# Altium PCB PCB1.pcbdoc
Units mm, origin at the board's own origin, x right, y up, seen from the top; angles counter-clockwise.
Board outline 140.58 x 68.45 mm, 2 copper layers (Top Layer, Bottom Layer); 49 components, 39 nets, 167 pads, 0 vias.
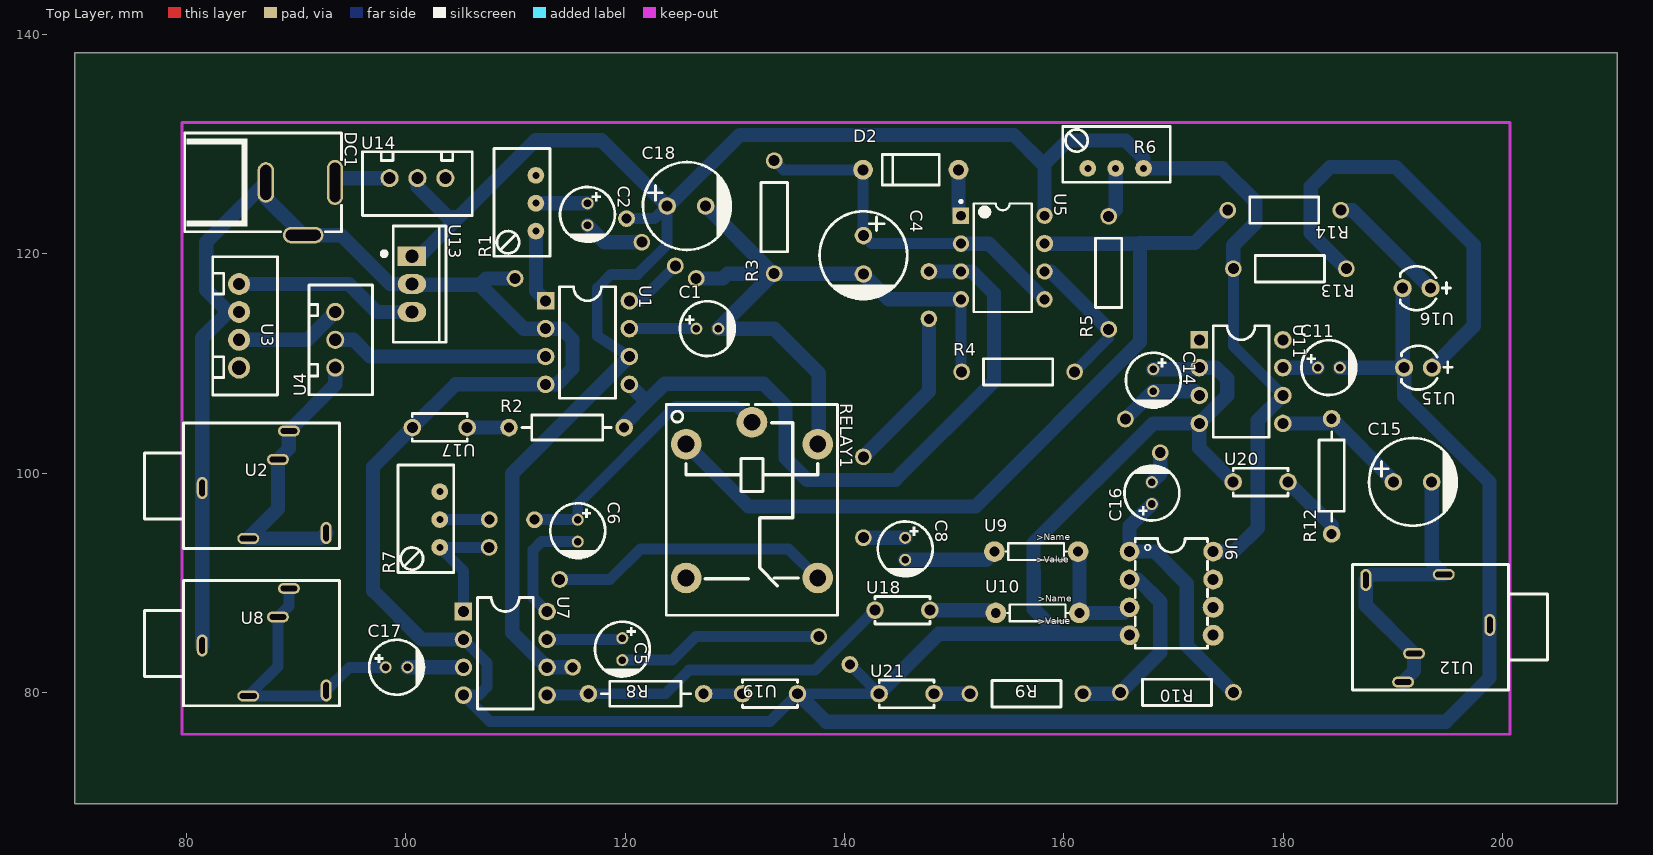
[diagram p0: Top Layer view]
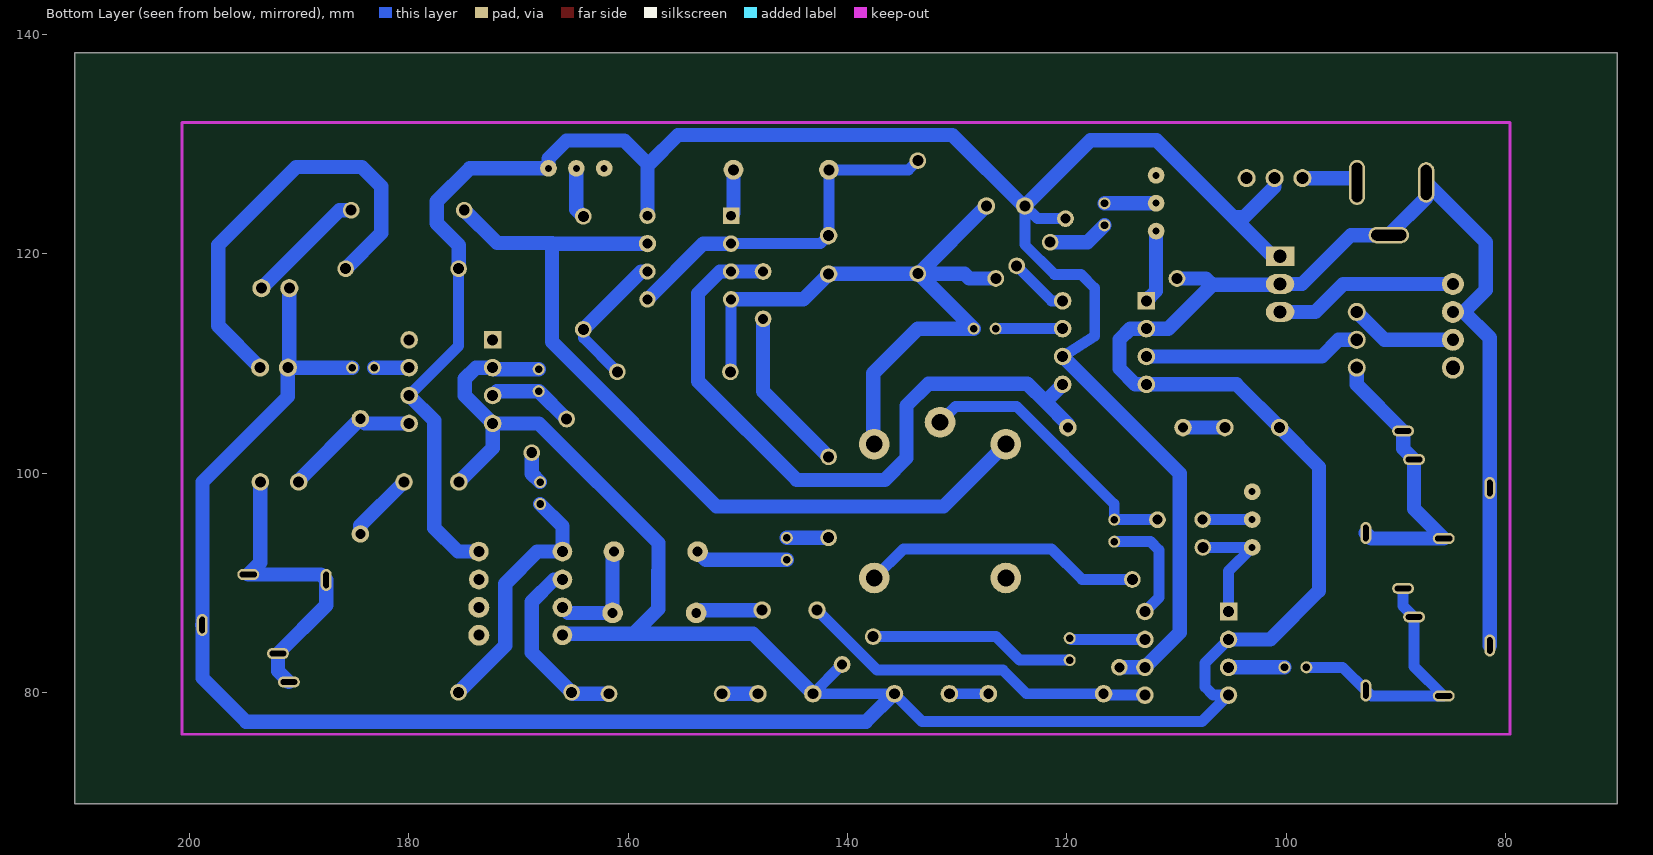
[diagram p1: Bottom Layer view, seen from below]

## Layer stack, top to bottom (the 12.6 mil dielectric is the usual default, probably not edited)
Top Layer: signal copper (thickness not stored)
Dielectric: dielectric 0.32, FR-4, Dk 4.8
Bottom Layer: signal copper (thickness not stored)

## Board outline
210.431,69.85 69.85,69.85 69.85,138.303 210.431,138.303

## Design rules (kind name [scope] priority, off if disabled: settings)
BoardOutlineClearance copperThickness1oz [All] p0: genericclearance=0.254 ignorepadtopadclearanceinfootprint=FALSE except(0: Arc-SplitContinuation Track-SplitContinuation SMDPad-SplitContinuation THPad-SplitContinuation Via-SplitContinuation Fill-SplitContinuation Poly-SplitContinuation Region-SplitContinuation Text-SplitContinuation; 0.152: Track-CutoutEdge SMDPad-CutoutEdge THPad-CutoutEdge Via-CutoutEdge Region-CutoutEdge; 0.3: Track-OutlineEdge SMDPad-OutlineEdge THPad-OutlineEdge Via-OutlineEdge Fill-OutlineEdge Region-OutlineEdge Poly-OutlineEdge Text-OutlineEdge Fill-CutoutEdge)
BoardOutlineClearance copperThickness2oz [All] p0: genericclearance=0.254 ignorepadtopadclearanceinfootprint=FALSE except(0: Arc-SplitContinuation Track-SplitContinuation SMDPad-SplitContinuation THPad-SplitContinuation Via-SplitContinuation Fill-SplitContinuation Poly-SplitContinuation Region-SplitContinuation Text-SplitContinuation; 0.152: Track-CutoutEdge SMDPad-CutoutEdge THPad-CutoutEdge Via-CutoutEdge Region-CutoutEdge; 0.3: Track-OutlineEdge SMDPad-OutlineEdge THPad-OutlineEdge Via-OutlineEdge Fill-OutlineEdge Region-OutlineEdge Poly-OutlineEdge Text-OutlineEdge Fill-CutoutEdge)
Clearance copperThickness1oz [(InNet('$1N574') OR InNet('GND') OR InNet('$1N680') OR InNet('$1N684') OR InNet('$1N813') OR InNet('$1N1432') OR InNet('$1N2090') OR InNet('$1N2102') OR InNet('$1N2104') OR InNet('$1N2109') OR InNet('$1N817') OR InNet('$1N2435') OR InNet('$1N2111') OR InNet('$1N2431') OR InNet('$1N2882') OR InNet('$1N2880') OR InNet('$1N2902') OR InNet('$1N3117') OR InNet('$1N2885') OR InNet('OU') OR InNet('$1N3248') OR InNet('$1N3253') OR InNet('VCC') OR InNet('$1N1428') OR InNet('$1N3436') OR InNet('$1N627') OR InNet('$1N1660') OR InNet('$1N1731') OR InNet('$1N2093') OR InNet('$1N2617') OR InNet('$1N3953') OR InNet('$1N4015') OR InNet('SOUNDON') OR InNet('$1N513') OR InNet('$1N880') OR InNet('+5V') OR InNet('$1N976') OR InNet('$1N2440') OR InNet('$1N4436'))] p1: gap=0.178 ignorepadtopadclearanceinfootprint=FALSE except(0.152: Track-SMDPad SMDPad-SMDPad Track-THPad SMDPad-THPad THPad-THPad Track-Via SMDPad-Via THPad-Via Via-Via SMDPad-Fill THPad-Fill Via-Fill Fill-Fill Track-Region SMDPad-Region THPad-Region Via-Region Region-Region Track-Poly SMDPad-Poly THPad-Poly Via-Poly Fill-Poly Region-Poly Poly-Poly Track-Text SMDPad-Text THPad-Text Via-Text Fill-Text Region-Text Poly-Text Text-Text; 0.175: Track-Hole SMDPad-Hole THPad-Hole Via-Hole Fill-Hole Region-Hole Poly-Hole Text-Hole Sheet-Hole; 0.3: Track-Fill Fill-Region Track-Sheet SMDPad-Sheet THPad-Sheet Via-Sheet Fill-Sheet Region-Sheet Poly-Sheet Text-Sheet; 1.001: Track-Track)
Clearance copperThickness2oz [All] p1: gap=0.178 ignorepadtopadclearanceinfootprint=FALSE except(0.152: Track-SMDPad SMDPad-SMDPad Track-THPad SMDPad-THPad THPad-THPad Track-Via SMDPad-Via THPad-Via Via-Via SMDPad-Fill THPad-Fill Via-Fill Fill-Fill Track-Region SMDPad-Region THPad-Region Via-Region Region-Region Track-Poly SMDPad-Poly THPad-Poly Via-Poly Fill-Poly Region-Poly Poly-Poly Track-Text SMDPad-Text THPad-Text Via-Text Fill-Text Region-Text Poly-Text Text-Text; 0.175: Track-Hole SMDPad-Hole THPad-Hole Via-Hole Fill-Hole Region-Hole Poly-Hole Text-Hole Sheet-Hole; 0.203: Track-Track; 0.3: Track-Fill Fill-Region Track-Sheet SMDPad-Sheet THPad-Sheet Via-Sheet Fill-Sheet Region-Sheet Poly-Sheet Text-Sheet)
DiffPairsRouting differentialPair [All] p1: maxuncoupledlength=10 minlimit=6 maxlimit=6 mostfreqgap=6 toplayer_minwidth=5 toplayer_prefwidth=10 toplayer_maxwidth=100 bottomlayer_minwidth=5 bottomlayer_prefwidth=10 bottomlayer_maxwidth=100
PasteMaskExpansion pasteMaskExpansion [All] p1: expansion=0
PlaneConnect innerPlane [All] p1: planeconnectstyle=Relief reliefexpansion=0.508 reliefentries=4 reliefconductorwidth=0.254 reliefairgap=0.254
PolygonConnect copperRegion [All] p1: connectstyle=Relief reliefentries=4 reliefconductorwidth=10 polygonreliefangle="90 Angle" airgapwidth=10
RoutingVias viaSize [All] p1: viastyle="Through Hole" holewidth=12.0078 minholewidth=11.811 maxholewidth=248.0314 width=24.0158 minwidth=19.685 maxwidth=393.7008
SolderMaskExpansion solderMaskExpansion [All] p1: useseparateexpansions=TRUE expansion=2 expansionbottom=2
Width copperThickness1oz [All] p1: maxlimit=51 minlimit=51 preferedwidth=51
Width copperThickness2oz [All] p1: maxlimit=100 minlimit=8 preferedwidth=10

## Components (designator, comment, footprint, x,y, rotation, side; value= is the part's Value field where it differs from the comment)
C1 "RYHT25V10UF5*8" CAP-TH_BD5.0-P2.00-D0.5-FD 127.504,113.157 r0 top
C2 "RYHT25V10UF5*8" CAP-TH_BD5.0-P2.00-D0.5-FD 116.582,123.571 r270 top
C4 "470uF" CAP-TH_BD8.0-P3.50-D0.6-FD 141.728,119.888 r270 top
C5 "RYHT25V10UF5*8" CAP-TH_BD5.0-P2.00-D0.5-FD 119.757,83.947 r270 top
C6 "RYHT25V10UF5*8" CAP-TH_BD5.0-P2.00-D0.5-FD 115.693,94.742 r270 top
C8 "RYHT25V10UF5*8" CAP-TH_BD5.0-P2.00-D0.5-FD 145.538,93.091 r270 top
C11 "RYHT25V10UF5*8" CAP-TH_BD5.0-P2.00-D0.5-FD 184.146,109.601 r0 top
C14 "RYHT25V10UF5*8" CAP-TH_BD5.0-P2.00-D0.5-FD 168.144,108.458 r270 top
C15 "470uF" CAP-TH_BD8.0-P3.50-D0.6-FD 191.766,99.187 r0 top
C16 "RYHT25V10UF5*8" CAP-TH_BD5.0-P2.00-D0.5-FD 168.017,98.171 r90 top
C17 "RYHT25V10UF5*8" CAP-TH_BD5.0-P2.00-D0.5-FD 99.183,82.296 r0 top
C18 "470uF" CAP-TH_BD8.0-P3.50-D0.6-FD 125.599,124.333 r0 top
D2 "1N4007R" DO-41_BD2.4-L4.7-P8.70-D0.9-RD 146.046,127.635 r0 top
DC1 "DCJ200-10-A-K1-K" DC-IN-TH_DCJ200-10-A-K1-K 90.42,124.079 r270 top
R1 "Trim_2K" "68W TRIMMER POT" 113.153,119.761 r90 top
R2 "10K" 10K 114.677,104.14 r0 top
R3 "MFR-25JT-52-6K8" RES-TH_BD2.4-L6.3-P10.30-D0.6 133.6,123.317 r90 top
R4 "MFR-25JT-52-6K8" RES-TH_BD2.4-L6.3-P10.30-D0.6 155.825,109.22 r0 top
R5 "MFR-25JT-52-6K8" RES-TH_BD2.4-L6.3-P10.30-D0.6 164.08,118.237 r90 top
R6 "Trim_2K" "68W TRIMMER POT" 159.889,126.492 r0 top
R7 "Trim_2K" "68W TRIMMER POT" 104.39,90.932 r90 top
R8 "10K" 10K 121.916,79.883 r180 top
R9 "MFR-25JT-52-6K8" RES-TH_BD2.4-L6.3-P10.30-D0.6 156.587,79.883 r180 top
R10 "MFR-25JT-52-6K8" RES-TH_BD2.4-L6.3-P10.30-D0.6 170.303,80.01 r180 top
R12 "10K" 10K 184.4,99.695 r90 top
R13 "MFR-25JT-52-6K8" RES-TH_BD2.4-L6.3-P10.30-D0.6 180.59,118.618 r180 top
R14 "MFR-25JT-52-6K8" RES-TH_BD2.4-L6.3-P10.30-D0.6 180.082,123.952 r180 top
RELAY1 "SRD-12VDC-SL-C" RELAY-TH_SRD-XXVDC-XL-C 131.568,97.536 r270 top
U1 "LM386N-1/NOPB" DIP-8_L10.0-W6.5-P2.54-LS7.6-BL 116.582,111.887 r270 top
U2 "PJ-324M0" AUDIO-TH_PJ-324-M 87.118,98.933 r0 top
U3 "XH2.54-4PIN" CONN-TH_XH2.54-4 84.832,113.411 r270 top
U4 "XH2.54_3PIN_立式" CONN-TH_XH2.54_3PIN 93.595,112.141 r90 top
U5 "LM358GN" DIP-8_L9.8-W6.6-P2.54-LS7.6-BL 154.428,119.634 r270 top
U6 "NE5532" PDIP-8_L9.6-W6.4-P2.54-LS7.6-BL-1 169.795,89.027 r270 top
U7 "LM386N-1/NOPB" DIP-8_L10.0-W6.5-P2.54-LS7.6-BL 109.089,83.566 r270 top
U8 "PJ-324M0" AUDIO-TH_PJ-324-M 87.118,84.582 r0 top
U9 "330OHM_-HORIZ-1/10W-5%" AXIAL-0.3 157.476,92.837 r0 top
U10 "330OHM_-HORIZ-1/10W-5%" AXIAL-0.3 157.603,87.249 r0 top
U11 "LM386N-1/NOPB" DIP-8_L10.0-W6.5-P2.54-LS7.6-BL 176.145,108.331 r270 top
U12 "PJ-324M0" AUDIO-TH_PJ-324-M 193.163,85.852 r180 top
U13 "LM7805" TO-220-3_L10.0-W4.5-P2.54-L 100.58,117.221 r270 top
U14 "XH2.54_3PIN_立式" CONN-TH_XH2.54_3PIN 101.088,126.873 r0 top
U15 "LED" LED-TH_BD4.0-P2.54-FD_RED 192.274,109.601 r180 top
U16 "LED" LED-TH_BD4.0-P2.54-FD_RED 192.147,116.84 r180 top
U17 "100nF" CAP-TH_L5.0-W2.5-P5.00-D1.0 103.12,104.14 r180 top
U18 "100nF" CAP-TH_L5.0-W2.5-P5.00-D1.0 145.284,87.503 r0 top
U19 "100nF" CAP-TH_L5.0-W2.5-P5.00-D1.0 133.219,79.883 r180 top
U20 "100nF" CAP-TH_L5.0-W2.5-P5.00-D1.0 177.923,99.187 r0 top
U21 "100nF" CAP-TH_L5.0-W2.5-P5.00-D1.0 145.665,79.883 r0 top

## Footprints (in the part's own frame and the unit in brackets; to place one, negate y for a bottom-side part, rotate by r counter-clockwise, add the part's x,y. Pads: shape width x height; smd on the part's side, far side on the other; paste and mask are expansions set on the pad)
10K [mm]
  round 1.6 hole 0.914: 1(-5.25,0) 2(5.25,0)
  silkscreen extent -4.06,-1.14 4.06,1.14
"68W TRIMMER POT" [mil]
  round 60 hole 25: 1(90,50) 2(190,50) 3(290,50)
  silkscreen extent 0,0 386,200
AUDIO-TH_PJ-324-M [mm]
  oval 1x2 hole 0.5 slot 1.5 at 90 deg: 1(-5.65,-0.3) 4(5.65,-4.4)
  oval 2x1 hole 0.5 slot 1.5 at 0 deg: 2(2.25,4.9) 3(1.25,2.3)
  oval 2x1 hole 0.5 slot 1.575 at 0 deg: 5(-1.45,-4.9)
  silkscreen extent -10.92,-5.8 6.86,5.63
AXIAL-0.3 [mil]
  round 74 hole 35.43: P$1(-150,0) P$2(150,0)
  silkscreen extent -110,-30 110,30
CAP-TH_BD5.0-P2.00-D0.5-FD [mm]
  round 1.1 hole 0.7: 1(-1,0) 2(1,0)
  silkscreen extent -2.5,-2.5 2.5,2.5
CAP-TH_BD8.0-P3.50-D0.6-FD [mm]
  round 1.6 hole 1: 1(-1.75,0) 2(1.75,0)
  silkscreen extent -3.96,-4 4.04,4
CAP-TH_L5.0-W2.5-P5.00-D1.0 [mm]
  round 1.6 hole 1: 1(-2.5,0) 2(2.5,0)
  silkscreen extent -2.5,-1.27 2.5,1.25
CONN-TH_XH2.54-4 [mm]
  round 2 hole 1.1: 1(-3.81,0) 2(-1.27,0) 3(1.27,0)
  round 2 hole 1.3: 4(3.81,0)
  silkscreen extent -6.3,-2.4 6.3,3.5
CONN-TH_XH2.54_3PIN [mm]
  round 1.65 hole 1.1: 1(-2.54,0) 2(0,0) 3(2.54,0)
  silkscreen extent -5,-3.4 5,2.4
DC-IN-TH_DCJ200-10-A-K1-K [mm]
  oval 4.1x1.5 hole 1 slot 3.6 at 0 deg: 1(-2.4,3.15)
  oval 1.5x3.7 hole 1 slot 3.2 at 90 deg: 2(2.4,0.25)
  oval 3.7x1.5 hole 1 slot 3.2 at 0 deg: 3(-2.4,-3.15)
  silkscreen extent -6.9,-10.55 2.1,3.75
DIP-8_L9.8-W6.6-P2.54-LS7.6-BL [mm]
  rect 1.5x1.5 hole 0.9: 1(-3.81,-3.81)
  round 1.5 hole 0.9: 2(-1.27,-3.81) 3(1.27,-3.81) 4(3.81,-3.81) 5(3.81,3.81) 6(1.27,3.81) 8(-3.81,3.81)
  round 1.575 hole 0.9: 7(-1.27,3.81)
  silkscreen extent -5.23,-3.93 4.96,2.65
DIP-8_L10.0-W6.5-P2.54-LS7.6-BL [mil]
  rect 63x63 hole 39.37: 1(-150,-150)
  round 63 hole 39.37: 2(-50,-150) 3(50,-150) 4(150,-150) 5(150,150) 6(50,150) 7(-50,150) 8(-150,150)
  silkscreen extent -200,-100 200,100
DO-41_BD2.4-L4.7-P8.70-D0.9-RD [mm]
  round 1.8 hole 1: 1(-4.35,0) 2(4.35,0)
  silkscreen extent -2.6,-1.4 2.6,1.4
LED-TH_BD4.0-P2.54-FD_RED [mil]
  round 65 hole 39.37: 1(-50,0) 2(50,0)
  silkscreen extent -122,-79 59,79
PDIP-8_L9.6-W6.4-P2.54-LS7.6-BL-1 [mm]
  round 1.8 hole 1: 1(-3.81,-3.81) 2(-1.27,-3.81) 3(1.27,-3.81) 4(3.81,-3.81) 7(-1.27,3.81) 8(-3.81,3.81)
  round 1.905 hole 1: 5(3.81,3.81) 6(1.27,3.81)
  silkscreen extent -5,-3.3 5,3.3
RELAY-TH_SRD-XXVDC-XL-C [mil]
  round 110 hole 60: 1(-200.79,-236.22) 2(279.53,-236.2) 3(279.53,236.2) 4(-200.79,236.22) 5(-279.53,0)
  silkscreen extent -342,-307 413,307
RES-TH_BD2.4-L6.3-P10.30-D0.6 [mm]
  round 1.524 hole 1: 1(-5.15,0) 2(5.15,0)
  silkscreen extent -3.15,-1.2 3.15,1.2
TO-220-3_L10.0-W4.5-P2.54-L [mm]
  rect 1.8x2.6 hole 1.2: 1(-2.54,0.005)
  oval 1.8x2.6 hole 1.2: 2(0,0.005) 3(2.54,-0.005)
  silkscreen extent -5.3,-2.73 5.3,3.09

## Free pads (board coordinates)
  round 1.524 hole 1: 1(107.613,93.218) 1(109.978,117.729) 1(114.042,90.297) 1(121.535,121.031) 1(126.488,117.729) 1(137.664,85.09) 1(141.728,101.473) 1(165.604,104.918) 1(168.779,101.854) 2(124.583,118.872) 2(141.728,94.107)
  round 1.524 hole 0.914: 1(107.636,95.758) 1(115.229,82.296) 1(120.138,123.19) 1(140.498,82.55) 1(147.697,118.364) 2(111.756,95.742) 2(147.697,114.046)

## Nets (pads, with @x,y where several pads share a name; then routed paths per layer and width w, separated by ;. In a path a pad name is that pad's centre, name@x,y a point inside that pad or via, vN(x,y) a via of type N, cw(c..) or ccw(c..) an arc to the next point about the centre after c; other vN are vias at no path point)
$1N513: U1.3 U4.2 | length 19.8
  Bottom Layer w1.3: U4.2 95.248,112.141 96.772,110.617 U1.3
$1N574: C1.1 U1.7 | length 6.1
  Bottom Layer w1: U1.7 C1.1
$1N627: R1.1 U1.1 | length 6.7
  Bottom Layer w1.3: R1.1 111.883,116.586 U1.1
$1N680: C2.1 R1.2 | length 4.7
  Bottom Layer w1.3: R1.2 116.566,124.587 C2.1
$1N684: C2.2 pad.1@121.535,121.031 pad.2@124.583,118.872 U1.8 | length 11.1
  Bottom Layer w1: U1.8 121.408,115.697 pad.2@124.583,118.872
  Bottom Layer w1.3: C2.2 118.122,121.031 pad.1@121.535,121.031
$1N813: R2.1 U17.1 | length 3.8
  Bottom Layer w1.3: U17.1 R2.1
$1N817: C8.1 pad.1@141.728,101.473 pad.1@147.697,118.364 pad.2@141.728,94.107 pad.2@147.697,114.046 R2.2 U1.5 U5.3 | length 81.6
  Bottom Layer w1.3: R2.2 119.927,104.449 121.901,106.423 ; U1.5 121.901,106.568 121.901,106.423 ; pad.2@141.728,94.107 145.522,94.107 C8.1 ; pad.1@141.728,101.473 147.697,107.442 pad.2@147.697,114.046 ; pad.1@147.697,118.364 U5.3 151.618,118.364 153.618,116.364 153.618,108.364 144.618,99.364 136.618,99.364 134.618,101.364 134.618,106.14 132.618,108.14 123.618,108.14 121.901,106.423
$1N880: U2.2 U2.3 U2.4 U2.5 U4.1 | length 26.2
  Bottom Layer w1.3: U2.4 92.268,94.033 U2.5 88.368,96.733 U2.3 89.368,102.233 U2.2 93.595,108.06 U4.1
$1N976: U3.3 U4.3 | length 9.8
  Bottom Layer w1.3: U3.3 91.055,112.141 U4.3
$1N1428: D2.2 U5.1 | length 4.3
  Bottom Layer w1.3: D2.2 150.396,123.666 U5.1
$1N1432: C4.1 D2.1 R3.2 U5.2 U5.5 | length 33.4
  Bottom Layer w1: R3.2 134.432,127.635 D2.1 141.696,121.67 C4.1 142.462,120.904 U5.2
  Bottom Layer w1.3: U5.2 153.158,120.904 U5.5
$1N1660: R4.2 R5.1 U5.6 | length 13.2
  Bottom Layer w1: R4.2 164.08,112.325 R5.1
  Bottom Layer w1.3: U5.6 158.803,118.364 R5.1
$1N1731: R5.2 R6.2 | length 4.6
  Bottom Layer w1.3: R5.2 164.715,124.022 R6.2
$1N2090: C5.1 U7.7 | length 6.9
  Bottom Layer w1: U7.7 119.646,84.836 C5.1
$1N2093: pad.1@107.613,93.218 pad.1@114.042,90.297 R7.1 RELAY1.3 U7.1 | length 37
  Bottom Layer w1: U7.1 105.279,91.059 R7.1 pad.1@107.613,93.218 ; pad.1@114.042,90.297 118.614,90.297 121.408,93.091 134.912,93.091 RELAY1.3
$1N2102: C6.1 pad.1@107.636,95.758 pad.2@111.756,95.742 R7.2 RELAY1.5 | length 30
  Bottom Layer w1: R7.2 pad.1@107.636,95.758 ; pad.2@111.756,95.742 C6.1 115.693,97.155 124.583,106.045 130.159,106.045 RELAY1.5
$1N2104: C6.2 U7.8 | length 10.5
  Bottom Layer w1: U7.8 111.629,88.646 111.629,92.964 112.407,93.742 C6.2
$1N2109: R8.1 U19.2 | length 3.6
  Bottom Layer w1: R8.1 U19.2
$1N2111: R8.2 U7.5 U18.1 | length 33.1
  Bottom Layer w1: U7.5 116.539,79.756 116.666,79.883 123.694,79.883 125.853,82.042 137.323,82.042 U18.1
$1N2431: U10.P$1 U18.2 | length 6.1
  Bottom Layer w1.3: U18.2 153.539,87.503 U10.P$1
$1N2435: C8.2 U9.P$1 | length 8.4
  Bottom Layer w1.3: C8.2 152.92,92.091 U9.P$1
$1N2440: U6.3 U9.P$2 U10.P$2 | length 10.4
  Bottom Layer w1.3: U9.P$2 161.413,92.71 U10.P$2 165.477,87.249 U6.3
$1N2617: R9.1 R10.2 U6.2 | length 16.9
  Bottom Layer w1.3: R9.1 165.026,79.883 168.779,83.636 168.779,88.265 166.747,90.297 U6.2
$1N2880: R12.1 U20.2 | length 6.4
  Bottom Layer w1.3: U20.2 184.4,95.21 R12.1
$1N2882: C11.1 U11.7 | length 3.2
  Bottom Layer w1.3: U11.7 C11.1
$1N2885: C15.1 R12.2 U11.5 | length 12.7
  Bottom Layer w1.3: U11.5 183.976,104.521 R12.2 190.016,99.329 C15.1
$1N2902: C14.2 C16.2 pad.1@165.604,104.918 pad.1@168.779,101.854 U11.3 | length 11
  Bottom Layer w1.3: pad.1@165.604,104.902 165.604,104.918 C14.2 171.938,107.458 U11.3 ; C16.2 168.779,99.933 pad.1@168.779,101.854
$1N3117: C15.2 U12.2 U12.3 U12.4 U12.5 | length 27.7
  Bottom Layer w1.3: U12.2 191.913,81.952 U12.3 187.513,87.952 U12.4 188.013,90.752 U12.5 193.516,91.849 C15.2
$1N3248: C17.1 U8.2 U8.3 U8.4 U8.5 | length 24.9
  Bottom Layer w1: U8.2 89.368,87.882 U8.3 88.368,82.382 U8.5 92.268,79.682 U8.4 94.882,82.296 C17.1
$1N3253: C17.2 U7.3 | length 5.1
  Bottom Layer w1.3: C17.2 U7.3
$1N3436: DC1.1 U14.1 | length 5.1
  Bottom Layer w1.3: DC1.1 93.964,126.873 U14.1
$1N3953: R13.1 U15.1 | length 40.1
  Bottom Layer w1.3: R13.1 182.495,121.863 182.495,126.111 184.273,127.889 190.242,127.889 197.354,120.777 197.354,113.411 U15.1
$1N4015: R14.1 U16.1 | length 11.1
  Bottom Layer w1.3: R14.1 186.305,123.952 U16.1
$1N4436: R9.2 U21.2 | length 3.3
  Bottom Layer w1.3: U21.2 R9.2
+5V: U3.1 U13.3 | length 16.8
  Bottom Layer w1.3: U3.1 94.832,117.221 97.372,114.681 U13.3
GND: C1.2 C4.2 C5.2 C11.2 C14.1 C18.2 DC1.2 DC1.3 pad.1@109.978,117.729 pad.1@126.488,117.729 pad.1@137.664,85.09 pad.1@140.498,82.55 R3.1 R4.1 RELAY1.4 U1.2 U1.4 U2.1 U3.2 U5.4 U6.4 U7.2 U7.4 U8.1 U11.2 U11.4 U12.1 U13.2 U15.2 U16.2 U17.2 U19.1 U20.1 U21.1 | length 450.3
  Bottom Layer w1: U7.2 107.438,82.677 107.438,80.518 106.676,79.756 U7.4 107.692,77.343 133.219,77.343 135.719,79.843 U19.1 U21.1 pad.1@140.498,82.55 ; C5.2 124.345,82.947 126.488,85.09 pad.1@137.664,85.09 ; U5.4 150.618,109.277 R4.1
  Bottom Layer w1.3: U8.1 U2.1 81.468,112.317 83.832,114.681 ; U3.2 83.832,114.681 ; U7.2 101.469,84.836 97.024,89.281 97.024,100.544 U17.2 104.557,108.077 U1.4 113.772,108.077 115.225,109.53 115.225,112.157 114.225,113.157 U1.2 110.772,113.157 106.772,117.157 ; pad.1@109.978,117.729 107.344,117.729 106.772,117.157 ; pad.1@126.488,117.729 128.901,117.729 129.339,118.167 R3.1 141.699,118.167 144.042,115.824 U5.4 ; C18.2 133.514,118.168 133.514,118.167 C1.2 133.6,113.157 137.664,109.093 137.664,102.732 RELAY1.4 ; U19.1@135.769,79.893 138.319,77.343 194.814,77.343 198.789,81.318 U12.1@198.789,86.176 ; U21.1@143.342,80.06 148.626,85.344 160.146,85.344 ; U6.4@165.949,85.253 U6.4 ; U6.4@165.967,85.235 165.858,85.344 159.508,85.344 157.253,87.599 157.253,88.955 157.238,93.615 168.144,104.521 U11.4 ; C14.1 172.192,109.458 U11.2 173.859,109.601 174.875,108.585 174.875,107.061 U11.4 ; U20.1 172.335,102.275 U11.4 ; C11.2 U15.2 ; U16.2 190.877,109.728 U15.2 ; U12.1 U12.1@198.789,86.176 ; 83.832,114.681 81.832,116.681 81.832,117.841 81.832,121.041 DC1.3 87.27,125.079 DC1.2 94.127,121.679 98.585,117.221 U13.2 100.649,117.157 106.772,117.157 ; U15.2 191.004,106.969 198.789,99.184 U12.1@198.789,86.176
OU: C16.1 R10.1 U6.1 | length 23.3
  Bottom Layer w1.3: C16.1 165.985,95.139 U6.1 168.271,92.837 171.192,89.916 171.192,84.271 R10.1
SOUNDON: R14.2 RELAY1.1 U5.7 | length 77
  Bottom Layer w1.3: RELAY1.1 131.252,96.952 151.932,96.952 166.932,111.952 166.932,120.952 ; U5.7 166.884,120.904 ; R14.2 171.932,120.952 166.932,120.952 ; 166.884,120.904 166.932,120.952 ; 166.884,120.904 166.932,120.952
VCC: C18.1 pad.1@115.229,82.296 pad.1@120.138,123.19 R6.3 R13.2 U1.6 U5.8 U6.8 U7.6 U11.6 U13.1 U14.2 | length 199.6
  Bottom Layer w1: pad.1@120.138,123.19 122.706,123.19 C18.1 123.849,120.805 121.154,118.11 118.741,118.11 117.471,116.84 117.471,112.485 U1.6 ; R13.2 175.44,111.576 U11.6
  Bottom Layer w1.3: U13.1 101.277,119.761 104.849,123.333 ; U14.2 101.088,126.094 103.849,123.333 104.849,123.333 ; pad.1@115.229,82.296 U7.6 109.724,85.471 109.724,99.949 U1.6 ; C18.1 117.849,130.333 111.849,130.333 104.849,123.333 ; C18.1@123.976,124.333 130.453,130.81 155.444,130.81 158.069,128.185 ; U5.8 158.238,128.185 160.355,130.302 165.604,130.302 167.255,128.651 R6.3 174.44,127.762 177.44,124.762 177.44,122.762 175.44,120.762 R13.2 ; U6.8 175.51,92.837 177.669,94.996 177.669,104.775 U11.6
pads on no net: R1.3 R6.1 R7.3 RELAY1.2 U3.4 U6.5 U6.6 U6.7 U11.1 U11.8 U14.3

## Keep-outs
Board Outline Layer:
  lines w0.254: 79.625,76.2 200.656,76.2 200.656,131.953 79.625,131.953 79.625,76.2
